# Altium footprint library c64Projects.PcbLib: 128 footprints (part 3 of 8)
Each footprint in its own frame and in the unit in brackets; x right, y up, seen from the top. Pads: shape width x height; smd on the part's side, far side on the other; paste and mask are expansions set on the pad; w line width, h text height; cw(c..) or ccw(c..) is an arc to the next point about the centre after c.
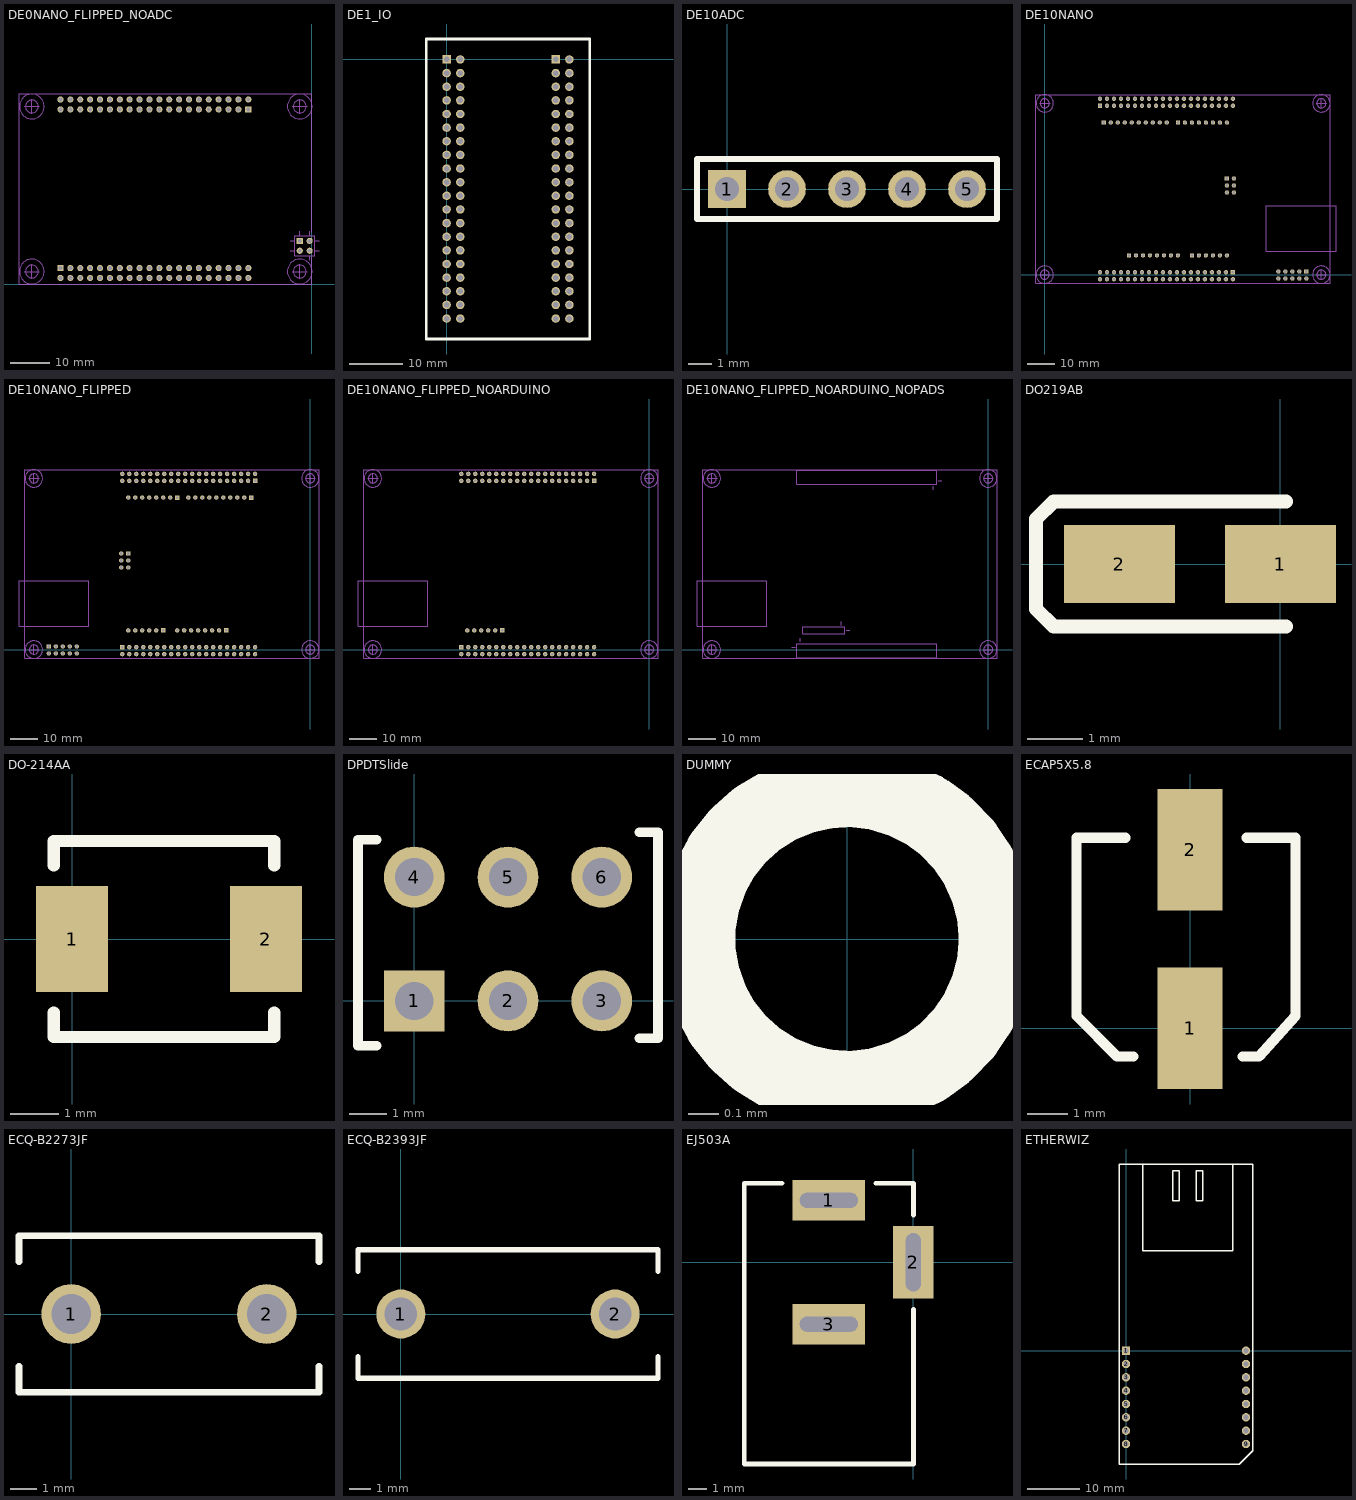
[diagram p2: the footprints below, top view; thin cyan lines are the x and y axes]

## DE0NANO_FLIPPED_NOADC [mil]
pads (84):
  rect 62x62 hole 38: A1(-640.16,1770.08) B1(-2540.16,164.96) D1(-120.08,440.16)
  round 62 hole 38: A2(-640.16,1870.08) A3(-740.16,1770.08) A4(-740.16,1870.08) A5(-840.16,1770.08) A6(-840.16,1870.08) A7(-940.16,1770.08) A8(-940.16,1870.08) A9(-1040.16,1770.08) A10(-1040.16,1870.08) A11(-1140.16,1770.08) A12(-1140.16,1870.08) A13(-1240.16,1770.08) A14(-1240.16,1870.08) A15(-1340.16,1770.08) A16(-1340.16,1870.08) A17(-1440.16,1770.08) A18(-1440.16,1870.08) A19(-1540.16,1770.08) A20(-1540.16,1870.08) A21(-1640.16,1770.08) A22(-1640.16,1870.08) A23(-1740.16,1770.08) A24(-1740.16,1870.08) A25(-1840.16,1770.08) A26(-1840.16,1870.08) A27(-1940.16,1770.08) A28(-1940.16,1870.08) A29(-2040.16,1770.08) A30(-2040.16,1870.08) A31(-2140.16,1770.08) A32(-2140.16,1870.08) A33(-2240.16,1770.08) A34(-2240.16,1870.08) A35(-2340.16,1770.08) A36(-2340.16,1870.08) A37(-2440.16,1770.08) A38(-2440.16,1870.08) A39(-2540.16,1770.08) A40(-2540.16,1870.08) B2(-2540.16,64.96) B3(-2440.16,164.96) B4(-2440.16,64.96) B5(-2340.16,164.96) B6(-2340.16,64.96) B7(-2240.16,164.96) B8(-2240.16,64.96) B9(-2140.16,164.96) B10(-2140.16,64.96) B11(-2040.16,164.96) B12(-2040.16,64.96) B13(-1940.16,164.96) B14(-1940.16,64.96) B15(-1840.16,164.96) B16(-1840.16,64.96) B17(-1740.16,164.96) B18(-1740.16,64.96) B19(-1640.16,164.96) B20(-1640.16,64.96) B21(-1540.16,164.96) B22(-1540.16,64.96) B23(-1440.16,164.96) B24(-1440.16,64.96) B25(-1340.16,164.96) B26(-1340.16,64.96) B27(-1240.16,164.96) B28(-1240.16,64.96) B29(-1140.16,164.96) B30(-1140.16,64.96) B31(-1040.16,164.96) B32(-1040.16,64.96) B33(-940.16,164.96) B34(-940.16,64.96) B35(-840.16,164.96) B36(-840.16,64.96) B37(-740.16,164.96) B38(-740.16,64.96) B39(-640.16,164.96) B40(-640.16,64.96) D2(-120.08,340.16) D3(-20.08,440.16) D4(-20.08,340.16)
Mechanical 3:
  circle w10: c-2829.92,129.92 r65
  circle w10: c-2829.92,129.92 r125
  circle w10: c-2829.92,1800 r65
  circle w10: c-2829.92,1800 r125
  circle w10: c-120.08,1800 r65
  circle w10: c-120.08,1800 r125
  circle w10: c-120.08,129.92 r65
  circle w10: c-120.08,129.92 r125
  lines w7.87: -170.08,490.16 29.92,490.16
  lines w8: -170.08,490.16 -170.08,290.16 29.92,290.16 29.92,490.16
  lines w10: -2904.92,129.92 -2754.92,129.92 ; -2904.92,1800 -2754.92,1800 ; -2829.92,54.92 -2829.92,204.92 ; -2829.92,1725 -2829.92,1875 ; -215,340 -170.08,340 ; -215,440 -170.08,440 ; -195.08,129.92 -45.08,129.92 ; -195.08,1800 -45.08,1800 ; -120.08,54.92 -120.08,204.92 ; -120.08,1725 -120.08,1875 ; -120,490.16 -120,540 ; -20,245 -20,290 ; -20,490 -20,540 ; 0,275 0,0 -2959.84,0 -2959.84,1929.92 0,1929.92 0,525 ; 30,340 75,340 ; 30,440 75,440
  text "4" at 65,320 h40
  text "3" at 65,485 h40
  text "2" at -250,320 h40
  text "1" at -250,480 h40

## DE1_IO [mil]
pads (80):
  rect 62x62 hole 40: A1(0,0) B1(800,0)
  round 62 hole 40: A2(100,0) A3(0,-100) A4(100,-100) A5(0,-200) A6(100,-200) A7(0,-300) A8(100,-300) A9(0,-400) A10(100,-400) A11(0,-500) A12(100,-500) A13(0,-600) A14(100,-600) A15(0,-700) A16(100,-700) A17(0,-800) A18(100,-800) A19(0,-900) A20(100,-900) A21(0,-1000) A22(100,-1000) A23(0,-1100) A24(100,-1100) A25(0,-1200) A26(100,-1200) A27(0,-1300) A28(100,-1300) A29(0,-1400) A30(100,-1400) A31(0,-1500) A32(100,-1500) A33(0,-1600) A34(100,-1600) A35(0,-1700) A36(100,-1700) A37(0,-1800) A38(100,-1800) A39(0,-1900) A40(100,-1900) B2(900,0) B3(800,-100) B4(900,-100) B5(800,-200) B6(900,-200) B7(800,-300) B8(900,-300) B9(800,-400) B10(900,-400) B11(800,-500) B12(900,-500) B13(800,-600) B14(900,-600) B15(800,-700) B16(900,-700) B17(800,-800) B18(900,-800) B19(800,-900) B20(900,-900) B21(800,-1000) B22(900,-1000) B23(800,-1100) B24(900,-1100) B25(800,-1200) B26(900,-1200) B27(800,-1300) B28(900,-1300) B29(800,-1400) B30(900,-1400) B31(800,-1500) B32(900,-1500) B33(800,-1600) B34(900,-1600) B35(800,-1700) B36(900,-1700) B37(800,-1800) B38(900,-1800) B39(800,-1900) B40(900,-1900)
Top Overlay:
  lines w20: -150,-2050 -150,150 1050,150 1050,-2050 -150,-2050

## DE10ADC [mil]
pads (5):
  rect 63x63 hole 40: 1(0,0)
  round 63 hole 40: 2(100,0) 3(200,0) 4(300,0) 5(400,0)
Top Overlay:
  lines w10: -50,-50 -50,50 450,50 450,-50 -50,-50

## DE10NANO [mil] "DE10 Nano Module"
pads (128):
  rect 62x62 hole 38: A1(789.37,2414.96) B1(2689.37,35.04) C1(844.49,2175.2) D1(1904.33,2175.2) E1(1204.33,275.2) F1(2104.33,275.2) G1(2604.33,1375.2) H1(3740.55,44.88)
  round 62 hole 38: A2(789.37,2514.96) A3(889.37,2414.96) A4(889.37,2514.96) A5(989.37,2414.96) A6(989.37,2514.96) A7(1089.37,2414.96) A8(1089.37,2514.96) A9(1189.37,2414.96) A10(1189.37,2514.96) A11(1289.37,2414.96) A12(1289.37,2514.96) A13(1389.37,2414.96) A14(1389.37,2514.96) A15(1489.37,2414.96) A16(1489.37,2514.96) A17(1589.37,2414.96) A18(1589.37,2514.96) A19(1689.37,2414.96) A20(1689.37,2514.96) A21(1789.37,2414.96) A22(1789.37,2514.96) A23(1889.37,2414.96) A24(1889.37,2514.96) A25(1989.37,2414.96) A26(1989.37,2514.96) A27(2089.37,2414.96) A28(2089.37,2514.96) A29(2189.37,2414.96) A30(2189.37,2514.96) A31(2289.37,2414.96) A32(2289.37,2514.96) A33(2389.37,2414.96) A34(2389.37,2514.96) A35(2489.37,2414.96) A36(2489.37,2514.96) A37(2589.37,2414.96) A38(2589.37,2514.96) A39(2689.37,2414.96) A40(2689.37,2514.96) B2(2689.37,-64.96) B3(2589.37,35.04) B4(2589.37,-64.96) B5(2489.37,35.04) B6(2489.37,-64.96) B7(2389.37,35.04) B8(2389.37,-64.96) B9(2289.37,35.04) B10(2289.37,-64.96) B11(2189.37,35.04) B12(2189.37,-64.96) B13(2089.37,35.04) B14(2089.37,-64.96) B15(1989.37,35.04) B16(1989.37,-64.96) B17(1889.37,35.04) B18(1889.37,-64.96) B19(1789.37,35.04) B20(1789.37,-64.96) B21(1689.37,35.04) B22(1689.37,-64.96) B23(1589.37,35.04) B24(1589.37,-64.96) B25(1489.37,35.04) B26(1489.37,-64.96) B27(1389.37,35.04) B28(1389.37,-64.96) B29(1289.37,35.04) B30(1289.37,-64.96) B31(1189.37,35.04) B32(1189.37,-64.96) B33(1089.37,35.04) B34(1089.37,-64.96) B35(989.37,35.04) B36(989.37,-64.96) B37(889.37,35.04) B38(889.37,-64.96) B39(789.37,35.04) B40(789.37,-64.96) C2(944.49,2175.2) C3(1044.49,2175.2) C4(1144.49,2175.2) C5(1244.49,2175.2) C6(1344.49,2175.2) C7(1444.49,2175.2) C8(1544.49,2175.2) C9(1644.49,2175.2) C10(1744.49,2175.2) D2(2004.33,2175.2) D3(2104.33,2175.2) D4(2204.33,2175.2) D5(2304.33,2175.2) D6(2404.33,2175.2) D7(2504.33,2175.2) D8(2604.33,2175.2) E2(1304.33,275.2) E3(1404.33,275.2) E4(1504.33,275.2) E5(1604.33,275.2) E6(1704.33,275.2) E7(1804.33,275.2) E8(1904.33,275.2) F2(2204.33,275.2) F3(2304.33,275.2) F4(2404.33,275.2) F5(2504.33,275.2) F6(2604.33,275.2) G2(2704.33,1375.2) G3(2604.33,1275.2) G4(2704.33,1275.2) G5(2604.33,1175.2) G6(2704.33,1175.2) H2(3740.55,-55.12) H3(3640.55,44.88) H4(3640.55,-55.12) H5(3540.55,44.88) H6(3540.55,-55.12) H7(3440.55,44.88) H8(3440.55,-55.12) H9(3340.55,44.88) H10(3340.55,-55.12)
Mechanical 3:
  circle w10: c3954.33,2450 r125
  circle w10: c3954.33,2450 r65
  circle w10: c3954.33,0 r125
  circle w10: c3954.33,0 r65
  circle w10: c0,0 r125
  circle w10: c0,0 r65
  circle w10: c0,2450 r125
  circle w10: c0,2450 r65
  lines w10: -75,0 75,0 ; -75,2450 75,2450 ; 0,-75 0,75 ; 0,2375 0,2525 ; 3879.33,0 4029.33,0 ; 3879.33,2450 4029.33,2450 ; 3954.33,-75 3954.33,75 ; 3954.33,2375 3954.33,2525 ; -125.2,-125.2 -125.2,2575.2 4084.25,2575.2 4084.25,-125.2 -125.2,-125.2 ; 3164.07,334.65 4164.07,334.65 4164.07,984.65 3164.07,984.65 3164.07,334.65

## DE10NANO_FLIPPED [mil]
pads (128):
  round 62 hole 38: -G6(-2704.33,1175.2) A2(-789.37,2514.96) A3(-889.37,2414.96) A4(-889.37,2514.96) A5(-989.37,2414.96) A6(-989.37,2514.96) A7(-1089.37,2414.96) A8(-1089.37,2514.96) A9(-1189.37,2414.96) A10(-1189.37,2514.96) A11(-1289.37,2414.96) A12(-1289.37,2514.96) A13(-1389.37,2414.96) A14(-1389.37,2514.96) A15(-1489.37,2414.96) A16(-1489.37,2514.96) A17(-1589.37,2414.96) A18(-1589.37,2514.96) A19(-1689.37,2414.96) A20(-1689.37,2514.96) A21(-1789.37,2414.96) A22(-1789.37,2514.96) A23(-1889.37,2414.96) A24(-1889.37,2514.96) A25(-1989.37,2414.96) A26(-1989.37,2514.96) A27(-2089.37,2414.96) A28(-2089.37,2514.96) A29(-2189.37,2414.96) A30(-2189.37,2514.96) A31(-2289.37,2414.96) A32(-2289.37,2514.96) A33(-2389.37,2414.96) A34(-2389.37,2514.96) A35(-2489.37,2414.96) A36(-2489.37,2514.96) A37(-2589.37,2414.96) A38(-2589.37,2514.96) A39(-2689.37,2414.96) A40(-2689.37,2514.96) B2(-2689.37,-64.96) B3(-2589.37,35.04) B4(-2589.37,-64.96) B5(-2489.37,35.04) B6(-2489.37,-64.96) B7(-2389.37,35.04) B8(-2389.37,-64.96) B9(-2289.37,35.04) B10(-2289.37,-64.96) B11(-2189.37,35.04) B12(-2189.37,-64.96) B13(-2089.37,35.04) B14(-2089.37,-64.96) B15(-1989.37,35.04) B16(-1989.37,-64.96) B17(-1889.37,35.04) B18(-1889.37,-64.96) B19(-1789.37,35.04) B20(-1789.37,-64.96) B21(-1689.37,35.04) B22(-1689.37,-64.96) B23(-1589.37,35.04) B24(-1589.37,-64.96) B25(-1489.37,35.04) B26(-1489.37,-64.96) B27(-1389.37,35.04) B28(-1389.37,-64.96) B29(-1289.37,35.04) B30(-1289.37,-64.96) B31(-1189.37,35.04) B32(-1189.37,-64.96) B33(-1089.37,35.04) B34(-1089.37,-64.96) B35(-989.37,35.04) B36(-989.37,-64.96) B37(-889.37,35.04) B38(-889.37,-64.96) B39(-789.37,35.04) B40(-789.37,-64.96) C2(-944.49,2175.2) C3(-1044.49,2175.2) C4(-1144.49,2175.2) C5(-1244.49,2175.2) C6(-1344.49,2175.2) C7(-1444.49,2175.2) C8(-1544.49,2175.2) C9(-1644.49,2175.2) C10(-1744.49,2175.2) D2(-2004.33,2175.2) D3(-2104.33,2175.2) D4(-2204.33,2175.2) D5(-2304.33,2175.2) D6(-2404.33,2175.2) D7(-2504.33,2175.2) D8(-2604.33,2175.2) E2(-1304.33,275.2) E3(-1404.33,275.2) E4(-1504.33,275.2) E5(-1604.33,275.2) E6(-1704.33,275.2) E7(-1804.33,275.2) E8(-1904.33,275.2) F2(-2204.33,275.2) F3(-2304.33,275.2) F4(-2404.33,275.2) F5(-2504.33,275.2) F6(-2604.33,275.2) G2(-2704.33,1375.2) G3(-2604.33,1275.2) G4(-2704.33,1275.2) G5(-2604.33,1175.2) H2(-3740.55,-55.12) H3(-3640.55,44.88) H4(-3640.55,-55.12) H5(-3540.55,44.88) H6(-3540.55,-55.12) H7(-3440.55,44.88) H8(-3440.55,-55.12) H9(-3340.55,44.88) H10(-3340.55,-55.12)
  rect 62x62 hole 38: A1(-789.37,2414.96) B1(-2689.37,35.04) C1(-844.49,2175.2) D1(-1904.33,2175.2) E1(-1204.33,275.2) F1(-2104.33,275.2) G1(-2604.33,1375.2) H1(-3740.55,44.88)
Mechanical 3:
  circle w10: c0,2450 r65
  circle w10: c0,2450 r125
  circle w10: c0,0 r65
  circle w10: c0,0 r125
  circle w10: c-3954.33,0 r65
  circle w10: c-3954.33,0 r125
  circle w10: c-3954.33,2450 r65
  circle w10: c-3954.33,2450 r125
  lines w10: -4029.33,0 -3879.33,0 ; -4029.33,2450 -3879.33,2450 ; -3954.33,-75 -3954.33,75 ; -3954.33,2375 -3954.33,2525 ; -75,0 75,0 ; -75,2450 75,2450 ; 0,-75 0,75 ; 0,2375 0,2525 ; 125.2,-125.2 -4084.25,-125.2 -4084.25,2575.2 125.2,2575.2 ; -4167.63,333.66 -3167.63,333.66 -3167.63,983.66 -4167.63,983.66 -4167.63,333.66
  lines w15: 125.2,-125.2 125.2,2575.2

## DE10NANO_FLIPPED_NOARDUINO [mil]
pads (86):
  rect 62x62 hole 38: A1(-789.37,2414.96) B1(-2689.37,35.04) F1(-2104.33,275.2)
  round 62 hole 38: A2(-789.37,2514.96) A3(-889.37,2414.96) A4(-889.37,2514.96) A5(-989.37,2414.96) A6(-989.37,2514.96) A7(-1089.37,2414.96) A8(-1089.37,2514.96) A9(-1189.37,2414.96) A10(-1189.37,2514.96) A11(-1289.37,2414.96) A12(-1289.37,2514.96) A13(-1389.37,2414.96) A14(-1389.37,2514.96) A15(-1489.37,2414.96) A16(-1489.37,2514.96) A17(-1589.37,2414.96) A18(-1589.37,2514.96) A19(-1689.37,2414.96) A20(-1689.37,2514.96) A21(-1789.37,2414.96) A22(-1789.37,2514.96) A23(-1889.37,2414.96) A24(-1889.37,2514.96) A25(-1989.37,2414.96) A26(-1989.37,2514.96) A27(-2089.37,2414.96) A28(-2089.37,2514.96) A29(-2189.37,2414.96) A30(-2189.37,2514.96) A31(-2289.37,2414.96) A32(-2289.37,2514.96) A33(-2389.37,2414.96) A34(-2389.37,2514.96) A35(-2489.37,2414.96) A36(-2489.37,2514.96) A37(-2589.37,2414.96) A38(-2589.37,2514.96) A39(-2689.37,2414.96) A40(-2689.37,2514.96) B2(-2689.37,-64.96) B3(-2589.37,35.04) B4(-2589.37,-64.96) B5(-2489.37,35.04) B6(-2489.37,-64.96) B7(-2389.37,35.04) B8(-2389.37,-64.96) B9(-2289.37,35.04) B10(-2289.37,-64.96) B11(-2189.37,35.04) B12(-2189.37,-64.96) B13(-2089.37,35.04) B14(-2089.37,-64.96) B15(-1989.37,35.04) B16(-1989.37,-64.96) B17(-1889.37,35.04) B18(-1889.37,-64.96) B19(-1789.37,35.04) B20(-1789.37,-64.96) B21(-1689.37,35.04) B22(-1689.37,-64.96) B23(-1589.37,35.04) B24(-1589.37,-64.96) B25(-1489.37,35.04) B26(-1489.37,-64.96) B27(-1389.37,35.04) B28(-1389.37,-64.96) B29(-1289.37,35.04) B30(-1289.37,-64.96) B31(-1189.37,35.04) B32(-1189.37,-64.96) B33(-1089.37,35.04) B34(-1089.37,-64.96) B35(-989.37,35.04) B36(-989.37,-64.96) B37(-889.37,35.04) B38(-889.37,-64.96) B39(-789.37,35.04) B40(-789.37,-64.96) F2(-2204.33,275.2) F3(-2304.33,275.2) F4(-2404.33,275.2) F5(-2504.33,275.2) F6(-2604.33,275.2)
Mechanical 3:
  circle w10: c-3954.33,0 r65
  circle w10: c-3954.33,0 r125
  circle w10: c0,0 r65
  circle w10: c0,0 r125
  circle w10: c0,2450 r65
  circle w10: c0,2450 r125
  circle w10: c-3954.33,2450 r65
  circle w10: c-3954.33,2450 r125
  lines w10: -4029.33,0 -3879.33,0 ; -4029.33,2450 -3879.33,2450 ; -3954.33,-75 -3954.33,75 ; -3954.33,2375 -3954.33,2525 ; -75,0 75,0 ; -75,2450 75,2450 ; 0,-75 0,75 ; 0,2375 0,2525 ; 125.2,-125.2 -4084.25,-125.2 -4084.25,2575.2 125.2,2575.2 ; -4167.63,333.66 -4167.63,983.66 -3167.63,983.66 -3167.63,333.66 -4167.63,333.66
  lines w15: 125.2,-125.2 125.2,2575.2

## DE10NANO_FLIPPED_NOARDUINO_NOPADS [mil]
Mechanical 3:
  circle w10: c0,2450 r65
  circle w10: c0,2450 r125
  circle w10: c0,0 r65
  circle w10: c0,0 r125
  circle w10: c-3954.33,0 r65
  circle w10: c-3954.33,0 r125
  circle w10: c-3954.33,2450 r65
  circle w10: c-3954.33,2450 r125
  lines w10: -4029.33,0 -3879.33,0 ; -4029.33,2450 -3879.33,2450 ; -3954.33,-75 -3954.33,75 ; -3954.33,2375 -3954.33,2525 ; -2814.37,35.04 -2764.37,35.04 ; -2689.37,110.04 -2689.37,160.04 ; -2104.33,350.2 -2104.33,400.2 ; -2029.33,275.2 -1979.33,275.2 ; -789.37,2289.96 -789.37,2339.96 ; -714.37,2414.96 -664.37,2414.96 ; -75,0 75,0 ; -75,2450 75,2450 ; 0,-75 0,75 ; 0,2375 0,2525 ; 125.2,-125.2 -4084.25,-125.2 -4084.25,2575.2 125.2,2575.2 ; -4167.63,333.66 -3167.63,333.66 -3167.63,983.66 -4167.63,983.66 -4167.63,333.66 ; -2739.37,-114.96 -739.37,-114.96 -739.37,85.04 -2739.37,85.04 -2739.37,-114.96 ; -2739.37,2364.96 -2739.37,2564.96 -739.37,2564.96 -739.37,2364.96 -2739.37,2364.96 ; -2654.33,225.2 -2054.33,225.2 -2054.33,325.2 -2654.33,325.2 -2654.33,225.2
  lines w15: 125.2,-125.2 125.2,2575.2
  text "F Pads" at -2450,175 h40
  text "B Side" at -2850,-100 h40
  text "A Side" at -625,2525 h40

## DO219AB [mm]
pads (2):
  rect 2x1.4 smd: 1(0,0) 2(-2.9,0)
Top Overlay:
  lines w0.254: 0.1,-1.127 -3.4,-1.127 -4.08,-1.127 -4.4,-0.807 -4.4,0.807 -4.08,1.127 -3.4,1.127 0.1,1.127

## DO-214AA [mm]
pads (2):
  rect 1.5x2.2 smd: 1(0,0) 2(4.02,0)
Top Overlay:
  lines w0.254: -0.381,-1.524 -0.381,-2.032 4.191,-2.032 4.191,-1.524 ; -0.381,1.524 -0.381,2.032 4.191,2.032 4.191,1.524

## DPDTSlide [mil]
pads (6):
  rect 64x64 hole 40: 1(0,0)
  round 64 hole 40: 2(98.43,0) 3(196.85,0) 4(0,130) 5(98.43,130) 6(196.85,130)
Top Overlay:
  lines w10: -39.37,-47.17 -59.06,-47.17 -59.06,169.37 -39.37,169.37 ; 236.22,-39.37 255.91,-39.37 255.91,177.17 236.22,177.17

## DUMMY [mil]
Top Overlay:
  circle w10: c0,0 r19.68

## ECAP5X5.8 [mm]
pads (2):
  rect 1.6x3 smd: 1(0,0) 2(0,4.4)
Top Overlay:
  lines w0.254: -1.6,4.7 -2.8,4.7 -2.8,0.3 -1.8,-0.7 -1.4,-0.7 ; 1.3,-0.7 1.7,-0.7 2.6,0.3 2.6,4.7 1.4,4.7

## ECQ-B2273JF [mil]
pads (2):
  round 90 hole 60: 1(0,0) 2(295.28,0)
Top Overlay:
  lines w10: -78.74,-78.74 -78.74,-118.11 374.02,-118.11 374.02,-78.74 ; -78.74,78.74 -78.74,118.11 374.02,118.11 374.02,78.74
3D body: height 629.92, standoff 0, extent -68.9,-118.11 364.17,118.11

## ECQ-B2393JF [mil]
pads (2):
  round 90 hole 60: 1(0,0) 2(393.7,0)
Top Overlay:
  lines w10: -78.74,-78.74 -78.74,-118.11 472.44,-118.11 472.44,-78.74 ; -78.74,78.74 -78.74,118.11 472.44,118.11 472.44,78.74

## EJ503A [mm]
pads (3):
  rect 3.861x2.159 hole 0.8 slot 3.1 at 0 deg: 1(-4.5,3.3) 3(-4.5,-3.3)
  rect 2.159x3.861 hole 0.8 slot 3.1 at 90 deg: 2(0,0)
Top Overlay:
  lines w0.254: -7,4.2 -9,4.2 -9,-10.74 0,-10.74 0,-2.5 ; -2,4.2 0,4.2 0,2.5

## ETHERWIZ [mil]
pads (16):
  rect 63x63 hole 40: 1(0,0)
  round 63 hole 40: 2(0,-100) 3(0,-200) 4(0,-300) 5(0,-400) 6(0,-500) 7(0,-600) 8(0,-700) 9(900,-700) 10(900,-600) 11(900,-500) 12(900,-400) 13(900,-300) 14(900,-200) 15(900,-100) 16(900,0)
Top Overlay:
  lines w10: 125,1400 125,750 800,750 800,1400 ; -50,-850 800,-850 850,-850 950,-750 950,1400 -50,1400 -50,-850 ; 350,1125 350,1350 400,1350 400,1125 350,1125 ; 525,1125 575,1125 575,1350 525,1350 525,1125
